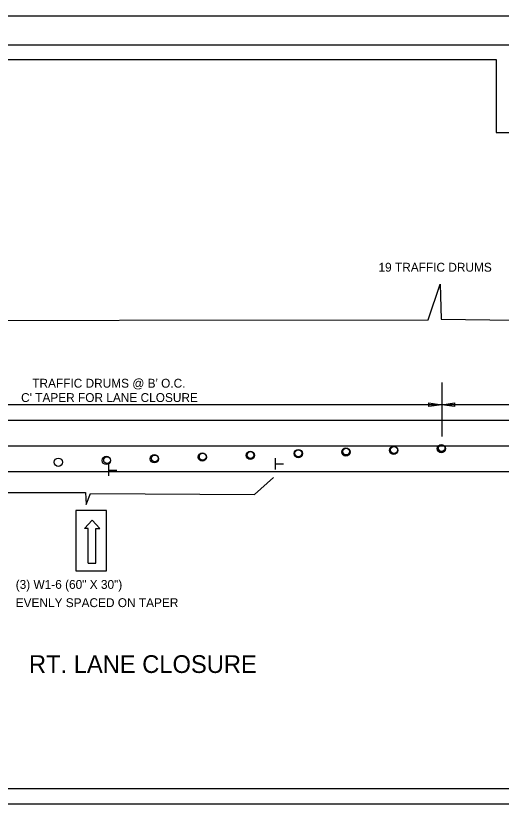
# Model space of a CAD drawing. Extents: x 1373222 to 1374279, y 380783 to 380996.
# Drawn here: x 1373782.6 to 1373848.3, y 380888.9 to 380996.5 of the extents above; entities that cross this region are included whole.
import ezdxf

# ---------------------------------------------------------------- set-up
doc = ezdxf.new("R2010")
doc.units = 0
for name, color, linetype in [('Default', 7, 'Continuous'), ('R_Border', 7, 'Continuous'), ('R_Border Plan-Plan', 7, 'Continuous'), ('R_No Plot', 7, 'Continuous')]:
    doc.layers.add(name, color=color, linetype=linetype)

msp = doc.modelspace()

# ---------------------------------------------------------------- linework, layer by layer
at = {"layer": 'Default'}
for p, q in [((1373840.26, 380946.87), (1373840.26, 380939.56)), ((1373838.52, 380943.6), (1373838.52, 380944.12)), ((1373838.52, 380944.12), (1373840.26, 380943.86)), ((1373840.26, 380943.86), (1373842, 380944.12)), ((1373842, 380944.12), (1373842, 380943.6)), ((1373840.26, 380943.86), (1373749.86, 380943.86)), ((1373840.26, 380943.86), (1373838.52, 380943.6)), ((1373892.42, 380943.86), (1373840.26, 380943.86)), ((1373842, 380943.6), (1373840.26, 380943.86)), ((1373608.96, 380941.78), (1373892.42, 380941.78)), ((1373608.96, 380938.31), (1373892.42, 380938.31)), ((1373817.75, 380935.09), (1373817.75, 380936.65)), ((1373795.21, 380934.24), (1373795.21, 380935.8)), ((1373817.77, 380935.87), (1373818.84, 380935.87)), ((1373608.96, 380934.83), (1373892.42, 380934.83)), ((1373795.23, 380935.01), (1373796.3, 380935.01)), ((1373791.9, 380927.09), (1373792.94, 380928.23)), ((1373792.94, 380928.23), (1373793.98, 380927.09)), ((1373792.42, 380927.09), (1373791.9, 380927.09)), ((1373792.42, 380922.43), (1373792.42, 380927.09)), ((1373793.46, 380922.43), (1373793.46, 380927.09)), ((1373793.46, 380927.09), (1373793.98, 380927.09)), ((1373792.42, 380922.43), (1373793.46, 380922.43))]:
    msp.add_line(p, q, dxfattribs=at)
for points in [[(1373750.83, 380950.03), (1373754.78, 380955.27), (1373838.44, 380955.36), (1373840.05, 380960.2), (1373840.19, 380955.43), (1373889.53, 380954.77), (1373891.81, 380949.57)], [(1373774.17, 380933.34), (1373776.49, 380931.98), (1373792.02, 380931.98), (1373792.15, 380930.34), (1373792.7, 380931.84), (1373814.9, 380931.71), (1373817.49, 380934.02)]]:
    msp.add_lwpolyline(points, dxfattribs=at)
msp.add_lwpolyline([(1373790.71, 380929.56), (1373790.71, 380921.38), (1373794.89, 380921.38), (1373794.89, 380929.56)], close=True, dxfattribs=at)
for centre, major_axis in [((1373814.36, 380937.01), (0, 0.563)), ((1373814.38, 380937.06), (0, 0.458)), ((1373820.86, 380937.25), (0, 0.563)), ((1373820.85, 380937.29), (0, 0.458)), ((1373827.3, 380937.47), (0, 0.563)), ((1373827.33, 380937.52), (0, 0.458)), ((1373833.76, 380937.69), (0, 0.563)), ((1373833.8, 380937.74), (0, 0.458)), ((1373840.21, 380937.91), (0, 0.563)), ((1373840.25, 380937.98), (0, 0.458)), ((1373840.28, 380937.97), (0, 0.458)), ((1373788.36, 380936.08), (0, 0.563)), ((1373794.86, 380936.32), (0, 0.563)), ((1373794.96, 380936.37), (0, 0.458)), ((1373801.36, 380936.55), (0, 0.563)), ((1373801.43, 380936.6), (0, 0.458)), ((1373807.86, 380936.78), (0, 0.563)), ((1373807.91, 380936.83), (0, 0.458))]:
    msp.add_ellipse(centre, major_axis=major_axis, ratio=0.99998, dxfattribs=at)
at = {"layer": 'R_Border'}
msp.add_line((1373596.1, 380992.59), (1373912.28, 380992.59), dxfattribs=at)
at = {"layer": 'R_Border Plan-Plan'}
msp.add_line((1373596.1, 380889.86), (1373912.28, 380889.86), dxfattribs=at)
at = {"layer": 'R_No Plot'}
for points in [[(1373583.69, 380996.49), (1373917.03, 380996.49), (1373917.03, 380783.15), (1373583.69, 380783.15)], [(1373910.28, 380891.86), (1373598.1, 380891.86), (1373598.1, 380990.59), (1373847.64, 380990.59), (1373847.64, 380980.71), (1373865.18, 380980.71), (1373889.28, 380980.71), (1373889.28, 380958.38), (1373910.28, 380958.38)], [(1373598.1, 380990.59), (1373847.64, 380990.59), (1373847.64, 380980.71), (1373865.18, 380980.71), (1373889.28, 380980.71), (1373889.28, 380958.38), (1373910.28, 380958.38), (1373910.28, 380789.13), (1373598.1, 380789.13)]]:
    msp.add_lwpolyline(points, close=True, dxfattribs=at)

# ---------------------------------------------------------------- texts
at = {"layer": 'Default'}
for s, height, p in [('19 TRAFFIC DRUMS', 1.2, (1373831.71, 380961.87)), ("TRAFFIC DRUMS @ B' O.C.", 1.2, (1373784.83, 380946.17)), ("C' TAPER FOR LANE CLOSURE", 1.2, (1373783.32, 380944.23)), ('RT. LANE CLOSURE', 2.4, (1373784.38, 380907.56))]:
    msp.add_text(s, height=height, dxfattribs=at).set_placement(p)
for s, p in [('(3) W1-6 (60" X 30")', (1373782.59, 380918.94)), ('EVENLY SPACED ON TAPER', (1373782.59, 380916.47))]:
    msp.add_text(s, height=1.2, rotation=0.0075, dxfattribs=at).set_placement(p)

doc.saveas('drawing.dxf')
